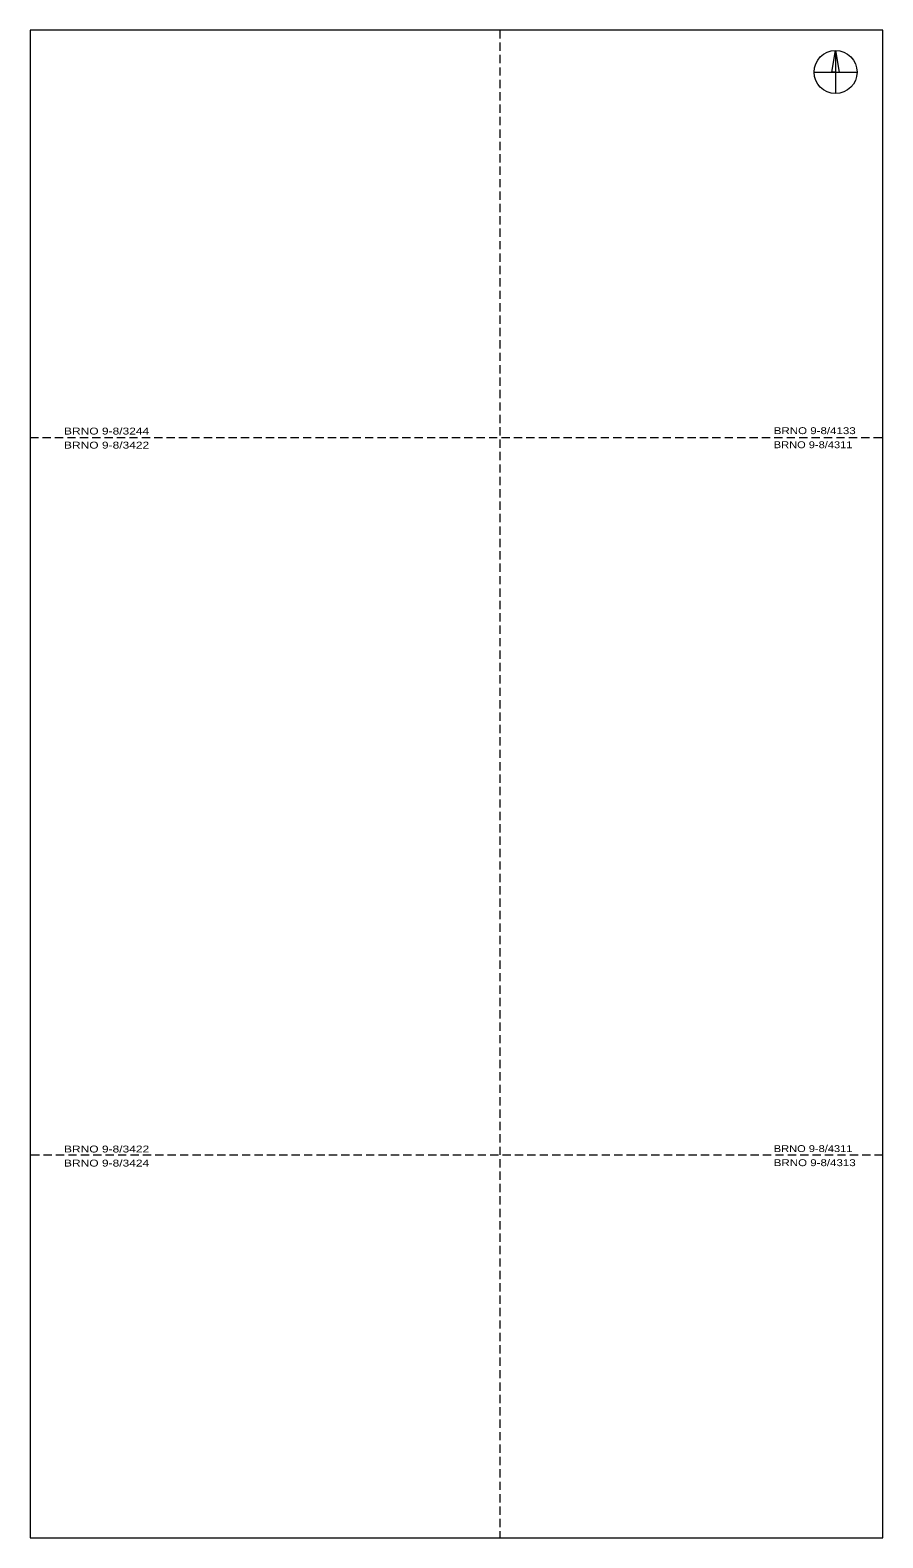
# Model space of a CAD drawing. Extents: x -598832 to -598683, y -1157692 to -1157429.
import ezdxf

# ---------------------------------------------------------------- set-up
doc = ezdxf.new("R2010")
doc.units = 0
doc.header["$LTSCALE"] = 0.48
doc.linetypes.add('MEDIUM_DASHED', pattern=[4.5, 3, -1.5])
for name, color, linetype, lineweight in [('1', 7, 'MEDIUM_DASHED', 13), ('2', 7, 'Continuous', 13), ('52', 7, 'Continuous', 13)]:
    doc.layers.add(name, color=color, linetype=linetype, lineweight=lineweight)

msp = doc.modelspace()

# ---------------------------------------------------------------- linework, layer by layer
at = {"layer": '1'}
for p, q in [((-598750, -1157429.1), (-598750, -1157691.6)), ((-598831.8, -1157500), (-598683.3, -1157500)), ((-598683.3, -1157625), (-598831.8, -1157625))]:
    msp.add_line(p, q, dxfattribs=at)
at = {"layer": '2'}
msp.add_lwpolyline([(-598831.8, -1157691.6), (-598683.3, -1157691.6), (-598683.3, -1157429.1), (-598831.8, -1157429.1)], close=True, dxfattribs=at)
at = {"layer": '52'}
for p, q in [((-598691.54, -1157432.65), (-598690.915, -1157436.4)), ((-598695.29, -1157436.4), (-598687.79, -1157436.4)), ((-598691.54, -1157436.4), (-598691.54, -1157440.15))]:
    msp.add_line(p, q, dxfattribs=at)
msp.add_lwpolyline([(-598691.54, -1157432.65), (-598691.54, -1157436.4), (-598692.165, -1157436.4)], close=True, dxfattribs=at)
msp.add_circle((-598691.54, -1157436.4), 3.75, dxfattribs=at)

# ---------------------------------------------------------------- texts
at = {"layer": '1'}
for s, width, p in [('BRNO 9-8/3244', 1.3, (-598825.907, -1157499.504)), ('BRNO 9-8/4133', 1.25, (-598702.297, -1157499.434)), ('BRNO 9-8/3422', 1.3, (-598825.907, -1157501.954)), ('BRNO 9-8/4311', 1.2, (-598702.297, -1157501.884)), ('BRNO 9-8/3422', 1.3, (-598825.907, -1157624.504)), ('BRNO 9-8/4311', 1.2, (-598702.297, -1157624.434)), ('BRNO 9-8/3424', 1.3, (-598825.907, -1157626.954)), ('BRNO 9-8/4313', 1.25, (-598702.297, -1157626.884))]:
    msp.add_text(s, height=1.2, dxfattribs=dict(at, width=width)).set_placement(p)

doc.saveas('drawing.dxf')
